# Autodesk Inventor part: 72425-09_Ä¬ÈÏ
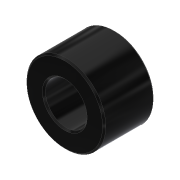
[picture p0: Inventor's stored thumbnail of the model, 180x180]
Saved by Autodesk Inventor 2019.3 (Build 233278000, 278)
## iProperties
Created: 2010-06
Part Number: 72425-09_Ä¬ÈÏ
Material: Ogólny
Document SubType Name: Modeling
Designer: CADENGINEERING4
Density: 1 g/cm^3
Appearance: Gładki — czarny
Author: CADENGINEERING4
Revision Number: ÈÎºÎ
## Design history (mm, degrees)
feature "NONE"
node "Bryła1"
